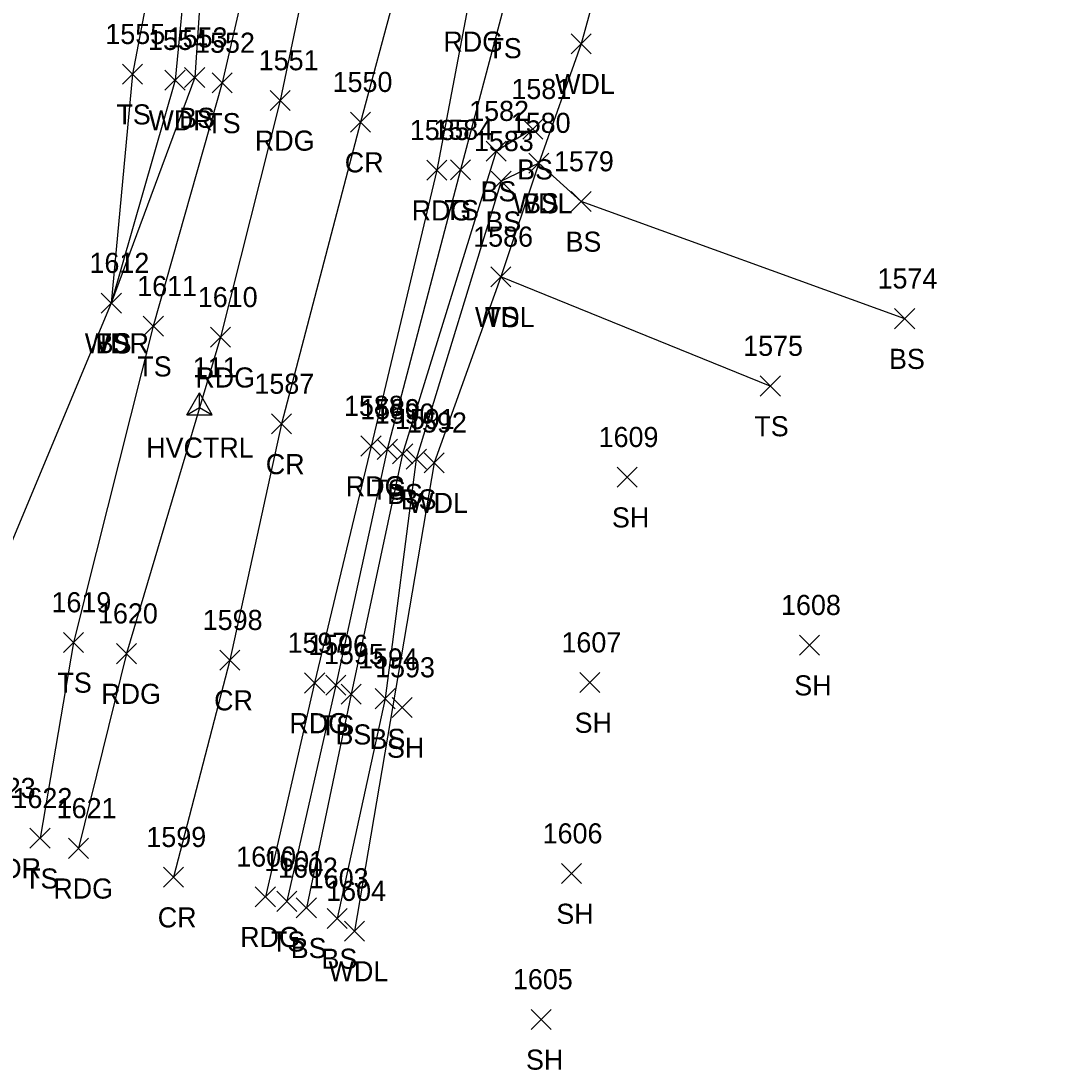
# Model space of a CAD drawing. Extents: x 1678553 to 1680768, y 787260 to 792325.
# Drawn here: x 1678621 to 1678723.5, y 787259.5 to 787363.9 of the extents above; entities that cross this region are included whole.
import ezdxf

# ---------------------------------------------------------------- set-up
doc = ezdxf.new("R2010")
doc.units = 0
for name, color, linetype in [('C_A', 7, 'Continuous'), ('C_I', 7, 'Continuous'), ('CPSM', 7, 'Continuous'), ('L_A', 7, 'Continuous'), ('L_I', 7, 'Continuous'), ('L_TIC', 7, 'Continuous'), ('LAWA', 7, 'Continuous'), ('LELB', 7, 'Continuous'), ('P_A', 7, 'Continuous'), ('P_I', 7, 'Continuous'), ('P_TIC', 7, 'Continuous'), ('PEU', 7, 'Continuous'), ('PRC', 7, 'Continuous')]:
    doc.layers.add(name, color=color, linetype=linetype)

msp = doc.modelspace()

# ---------------------------------------------------------------- linework, layer by layer
at = {"layer": 'CPSM'}
for p, q in [((1678637.53, 787324.73), (1678638.78, 787326.89)), ((1678640.03, 787324.73), (1678638.78, 787326.89)), ((1678638.78, 787325.45), (1678638.78, 787326.89)), ((1678637.53, 787324.73), (1678638.78, 787325.45)), ((1678637.53, 787324.73), (1678640.03, 787324.73)), ((1678638.78, 787325.45), (1678638.78, 787325.45)), ((1678638.78, 787325.45), (1678640.03, 787324.73))]:
    msp.add_line(p, q, dxfattribs=at)
at = {"layer": 'L_TIC'}
for points in [[(1678675.74, 787360.63), (1678677.74, 787362.63)], [(1678677.74, 787360.63), (1678675.74, 787362.63)], [(1678631.1, 787357.6), (1678633.1, 787359.6)], [(1678633.1, 787357.6), (1678631.1, 787359.6)], [(1678635.34, 787357.01), (1678637.34, 787359.01)], [(1678637.34, 787357.01), (1678635.34, 787359.01)], [(1678637.3, 787357.26), (1678639.3, 787359.26)], [(1678639.3, 787357.26), (1678637.3, 787359.26)], [(1678640.04, 787356.73), (1678642.04, 787358.73)], [(1678642.04, 787356.73), (1678640.04, 787358.73)], [(1678670.94, 787352.13), (1678672.94, 787354.13)], [(1678672.94, 787352.13), (1678670.94, 787354.13)], [(1678667.3, 787349.95), (1678669.3, 787351.95)], [(1678669.3, 787349.95), (1678667.3, 787351.95)], [(1678671.53, 787348.76), (1678673.53, 787350.76)], [(1678673.53, 787348.76), (1678671.53, 787350.76)], [(1678671.53, 787348.76), (1678673.53, 787350.76)], [(1678673.53, 787348.76), (1678671.53, 787350.76)], [(1678671.53, 787348.76), (1678673.53, 787350.76)], [(1678673.53, 787348.76), (1678671.53, 787350.76)], [(1678663.74, 787348.08), (1678665.74, 787350.08)], [(1678665.74, 787348.08), (1678663.74, 787350.08)], [(1678667.78, 787346.95), (1678669.78, 787348.95)], [(1678669.78, 787346.95), (1678667.78, 787348.95)], [(1678675.75, 787344.94), (1678677.75, 787346.94)], [(1678677.75, 787344.94), (1678675.75, 787346.94)], [(1678667.76, 787337.44), (1678669.76, 787339.44)], [(1678669.76, 787337.44), (1678667.76, 787339.44)], [(1678667.76, 787337.44), (1678669.76, 787339.44)], [(1678669.76, 787337.44), (1678667.76, 787339.44)], [(1678629, 787334.83), (1678631, 787336.83)], [(1678631, 787334.83), (1678629, 787336.83)], [(1678629, 787334.83), (1678631, 787336.83)], [(1678631, 787334.83), (1678629, 787336.83)], [(1678629, 787334.83), (1678631, 787336.83)], [(1678631, 787334.83), (1678629, 787336.83)], [(1678707.94, 787333.28), (1678709.94, 787335.28)], [(1678709.94, 787333.28), (1678707.94, 787335.28)], [(1678633.18, 787332.53), (1678635.18, 787334.53)], [(1678635.18, 787332.53), (1678633.18, 787334.53)], [(1678694.57, 787326.58), (1678696.57, 787328.58)], [(1678696.57, 787326.58), (1678694.57, 787328.58)], [(1678656.46, 787320.28), (1678658.46, 787322.28)], [(1678658.46, 787320.28), (1678656.46, 787322.28)], [(1678657.99, 787319.84), (1678659.99, 787321.84)], [(1678659.99, 787319.84), (1678657.99, 787321.84)], [(1678659.35, 787319.3), (1678661.35, 787321.3)], [(1678661.35, 787319.3), (1678659.35, 787321.3)], [(1678661.12, 787318.95), (1678663.12, 787320.95)], [(1678663.12, 787318.95), (1678661.12, 787320.95)], [(1678680.32, 787317.51), (1678682.32, 787319.51)], [(1678682.32, 787317.51), (1678680.32, 787319.51)], [(1678625.23, 787301.07), (1678627.23, 787303.07)], [(1678627.23, 787301.07), (1678625.23, 787303.07)], [(1678698.46, 787300.8), (1678700.46, 787302.8)], [(1678700.46, 787300.8), (1678698.46, 787302.8)], [(1678651.34, 787296.83), (1678653.34, 787298.83)], [(1678653.34, 787296.83), (1678651.34, 787298.83)], [(1678676.61, 787297.08), (1678678.61, 787299.08)], [(1678678.61, 787297.08), (1678676.61, 787299.08)], [(1678652.86, 787295.92), (1678654.86, 787297.92)], [(1678654.86, 787295.92), (1678652.86, 787297.92)], [(1678656.25, 787295.48), (1678658.25, 787297.48)], [(1678658.25, 787295.48), (1678656.25, 787297.48)], [(1678657.94, 787294.6), (1678659.94, 787296.6)], [(1678659.94, 787294.6), (1678657.94, 787296.6)], [(1678621.91, 787281.59), (1678623.91, 787283.59)], [(1678623.91, 787281.59), (1678621.91, 787283.59)], [(1678674.79, 787278.08), (1678676.79, 787280.08)], [(1678676.79, 787278.08), (1678674.79, 787280.08)], [(1678646.47, 787275.32), (1678648.47, 787277.32)], [(1678648.47, 787275.32), (1678646.47, 787277.32)], [(1678648.41, 787274.67), (1678650.41, 787276.67)], [(1678650.41, 787274.67), (1678648.41, 787276.67)], [(1678651.47, 787273.61), (1678653.47, 787275.61)], [(1678653.47, 787273.61), (1678651.47, 787275.61)], [(1678653.2, 787272.36), (1678655.2, 787274.36)], [(1678655.2, 787272.36), (1678653.2, 787274.36)], [(1678671.78, 787263.57), (1678673.78, 787265.57)], [(1678673.78, 787263.57), (1678671.78, 787265.57)]]:
    msp.add_lwpolyline(points, dxfattribs=at)
at = {"layer": 'LAWA'}
for points in [[(1678709.78, 787516.49), (1678712.28, 787497.22), (1678701.79, 787461.31), (1678703.15, 787457.42), (1678705.06, 787457.53), (1678706.33, 787458.18), (1678713.92, 787445.73), (1678717.92, 787439.61), (1678723.5, 787424.18), (1678713.91, 787402.7), (1678707.75, 787397.77), (1678697.86, 787399.45), (1678688.05, 787395.99), (1678683.78, 787387.21), (1678676.74, 787361.63), (1678672.53, 787349.76), (1678668.76, 787338.44), (1678662.12, 787319.95), (1678654.2, 787273.36)], [(1678664.87, 787478.76), (1678656.17, 787475.05), (1678649.55, 787452.64), (1678645.06, 787437.85), (1678645.53, 787417.53), (1678643.94, 787403.04), (1678640.14, 787385.56), (1678638.68, 787382.05), (1678636.34, 787358.01), (1678630, 787335.83), (1678617.26, 787305.35), (1678619.26, 787283.6)]]:
    msp.add_lwpolyline(points, dxfattribs=at)
at = {"layer": 'LELB'}
for points in [[(1678703.25, 787521.16), (1678708.08, 787504.89), (1678710.05, 787496.73), (1678699.74, 787468.92), (1678698.82, 787457.49), (1678706.75, 787433.93), (1678714.45, 787417.51), (1678705.65, 787404.22), (1678696.31, 787404.91), (1678687.53, 787400.61), (1678678.86, 787394.6), (1678669.01, 787365.19), (1678664.74, 787349.08), (1678657.46, 787321.28), (1678652.34, 787297.83), (1678647.47, 787276.32)], [(1678680.77, 787518.06), (1678676.3, 787498.71), (1678671.38, 787486.28), (1678667.84, 787478.11), (1678658.92, 787472.2), (1678652.16, 787452.17), (1678649.27, 787436.42), (1678649.32, 787416.12), (1678648.83, 787401.97), (1678646.78, 787382.69), (1678641.04, 787357.73), (1678634.18, 787333.53), (1678626.23, 787302.07), (1678622.91, 787282.59)], [(1678670.34, 787510.61), (1678668.53, 787502.63), (1678666.36, 787491.77), (1678660.38, 787481.94), (1678643.3, 787471.26), (1678637.93, 787460.78), (1678638.18, 787442.6), (1678641.03, 787418.21), (1678640, 787400.91), (1678637.64, 787392.16), (1678640.14, 787385.56), (1678638.3, 787358.26), (1678630, 787335.83)], [(1678606.34, 787416.23), (1678617.44, 787401.01), (1678626.85, 787385.47), (1678635.93, 787378.61), (1678632.1, 787358.6), (1678630, 787335.83)], [(1678671.94, 787353.13), (1678668.3, 787350.95), (1678658.99, 787320.84), (1678653.86, 787296.92), (1678649.41, 787275.67)], [(1678672.53, 787349.76), (1678668.78, 787347.95), (1678660.35, 787320.3), (1678657.25, 787296.48), (1678652.47, 787274.61)], [(1678708.94, 787334.28), (1678676.75, 787345.94), (1678672.53, 787349.76)], [(1678695.57, 787327.58), (1678668.76, 787338.44)]]:
    msp.add_lwpolyline(points, dxfattribs=at)
at = {"layer": 'P_TIC'}
for points in [[(1678645.8, 787354.99), (1678647.8, 787356.99)], [(1678647.8, 787354.99), (1678645.8, 787356.99)], [(1678653.8, 787352.83), (1678655.8, 787354.83)], [(1678655.8, 787352.83), (1678653.8, 787354.83)], [(1678661.4, 787348.05), (1678663.4, 787350.05)], [(1678663.4, 787348.05), (1678661.4, 787350.05)], [(1678639.87, 787331.43), (1678641.87, 787333.43)], [(1678641.87, 787331.43), (1678639.87, 787333.43)], [(1678645.93, 787322.81), (1678647.93, 787324.81)], [(1678647.93, 787322.81), (1678645.93, 787324.81)], [(1678654.84, 787320.61), (1678656.84, 787322.61)], [(1678656.84, 787320.61), (1678654.84, 787322.61)], [(1678630.51, 787299.96), (1678632.51, 787301.96)], [(1678632.51, 787299.96), (1678630.51, 787301.96)], [(1678640.79, 787299.31), (1678642.79, 787301.31)], [(1678642.79, 787299.31), (1678640.79, 787301.31)], [(1678649.23, 787297.04), (1678651.23, 787299.04)], [(1678651.23, 787297.04), (1678649.23, 787299.04)], [(1678625.74, 787280.59), (1678627.74, 787282.59)], [(1678627.74, 787280.59), (1678625.74, 787282.59)], [(1678635.19, 787277.72), (1678637.19, 787279.72)], [(1678637.19, 787277.72), (1678635.19, 787279.72)], [(1678644.33, 787275.77), (1678646.33, 787277.77)], [(1678646.33, 787275.77), (1678644.33, 787277.77)]]:
    msp.add_lwpolyline(points, dxfattribs=at)
at = {"layer": 'PEU'}
for points in [[(1678701.08, 787523.46), (1678691.86, 787521.67), (1678683.93, 787520.5), (1678679.42, 787498.09), (1678675.86, 787484.77), (1678672.35, 787466.03), (1678666.65, 787446.98), (1678662.98, 787430.65), (1678658.14, 787412.6), (1678657.12, 787400.24), (1678652, 787380.89), (1678646.8, 787355.99), (1678640.87, 787332.43), (1678631.51, 787300.96), (1678626.74, 787281.59)], [(1678701.08, 787523.46), (1678699.33, 787512.57), (1678697.82, 787495.04), (1678694.12, 787469.83), (1678689.97, 787450.94), (1678685.8, 787426.95), (1678675.55, 787395.19), (1678665.56, 787365.84), (1678662.4, 787349.05), (1678655.84, 787321.61), (1678650.23, 787298.04), (1678645.33, 787276.77)]]:
    msp.add_lwpolyline(points, dxfattribs=at)
at = {"layer": 'PRC'}
msp.add_lwpolyline([(1678691.86, 787521.67), (1678687.47, 787496.54), (1678683.41, 787472.73), (1678673.58, 787430.34), (1678667.07, 787403.39), (1678661.63, 787379.18), (1678654.8, 787353.83), (1678646.93, 787323.81), (1678641.79, 787300.31), (1678636.19, 787278.72)], dxfattribs=at)

# ---------------------------------------------------------------- texts
at = {"layer": 'C_A'}
msp.add_text('HVCTRL', height=2, dxfattribs=at).set_placement((1678633.47, 787320.45))
at = {"layer": 'C_I'}
msp.add_text('111', height=2, dxfattribs=at).set_placement((1678638.12, 787328.45))
at = {"layer": 'L_A'}
for s, p in [('TS', (1678667.42, 787360.19)), ('WDL', (1678674.16, 787356.63)), ('TS', (1678630.51, 787353.6)), ('WDR', (1678633.7, 787353.01)), ('BS', (1678636.74, 787353.26)), ('TS', (1678639.45, 787352.73)), ('BS', (1678670.38, 787348.13)), ('BS', (1678666.74, 787345.95)), ('WDL', (1678669.94, 787344.76)), ('BS', (1678670.97, 787344.76)), ('BS', (1678670.97, 787344.76)), ('TS', (1678663.15, 787344.08)), ('BS', (1678667.22, 787342.95)), ('BS', (1678675.19, 787340.94)), ('WDL', (1678666.18, 787333.44)), ('TS', (1678667.17, 787333.44)), ('WDR', (1678627.36, 787330.83)), ('TS', (1678628.41, 787330.83)), ('BS', (1678628.44, 787330.83)), ('BS', (1678707.38, 787329.28)), ('TS', (1678632.59, 787328.53)), ('TS', (1678693.98, 787322.58)), ('TS', (1678655.87, 787316.28)), ('BS', (1678657.43, 787315.84)), ('BS', (1678658.79, 787315.3)), ('WDL', (1678659.54, 787314.95)), ('SH', (1678679.81, 787313.51)), ('TS', (1678624.64, 787297.07)), ('SH', (1678697.95, 787296.8)), ('TS', (1678650.75, 787292.83)), ('SH', (1678676.1, 787293.08)), ('BS', (1678652.3, 787291.92)), ('BS', (1678655.69, 787291.48)), ('SH', (1678657.43, 787290.6)), ('WDR', (1678616.62, 787278.6)), ('TS', (1678621.32, 787277.59)), ('SH', (1678674.28, 787274.08)), ('TS', (1678645.88, 787271.32)), ('BS', (1678647.85, 787270.67)), ('BS', (1678650.91, 787269.61)), ('WDL', (1678651.62, 787268.36)), ('SH', (1678671.26, 787259.57))]:
    msp.add_text(s, height=2, dxfattribs=at).set_placement(p)
at = {"layer": 'L_I'}
for s, p in [('1555', (1678629.41, 787361.6)), ('1553', (1678635.61, 787361.26)), ('1554', (1678633.65, 787361.01)), ('1552', (1678638.34, 787360.73)), ('1581', (1678669.81, 787356.13)), ('1582', (1678665.61, 787353.95)), ('1580', (1678669.75, 787352.76)), ('1580', (1678669.75, 787352.76)), ('1580', (1678669.75, 787352.76)), ('1584', (1678662.04, 787352.08)), ('1583', (1678666.08, 787350.95)), ('1579', (1678674.05, 787348.94)), ('1586', (1678666.01, 787341.44)), ('1586', (1678666.01, 787341.44)), ('1612', (1678627.83, 787338.83)), ('1612', (1678627.83, 787338.83)), ('1612', (1678627.83, 787338.83)), ('1574', (1678706.24, 787337.28)), ('1611', (1678632.58, 787336.53)), ('1575', (1678692.87, 787330.58)), ('1589', (1678654.76, 787324.28)), ('1590', (1678656.21, 787323.84)), ('1591', (1678658.22, 787323.3)), ('1592', (1678659.43, 787322.95)), ('1609', (1678678.49, 787321.51)), ('1619', (1678624.05, 787305.07)), ('1608', (1678696.64, 787304.8)), ('1596', (1678649.59, 787300.83)), ('1607', (1678674.79, 787301.08)), ('1595', (1678651.16, 787299.92)), ('1594', (1678654.55, 787299.48)), ('1593', (1678656.25, 787298.6)), ('1623', (1678616.52, 787286.6)), ('1622', (1678620.17, 787285.59)), ('1606', (1678672.92, 787282.08)), ('1601', (1678645.21, 787279.32)), ('1602', (1678646.59, 787278.67)), ('1603', (1678649.65, 787277.61)), ('1604', (1678651.38, 787276.36)), ('1605', (1678669.96, 787267.57))]:
    msp.add_text(s, height=2, dxfattribs=at).set_placement(p)
at = {"layer": 'P_A'}
for s, p in [('RDG', (1678663.04, 787360.84)), ('RDG', (1678644.28, 787350.99)), ('CR', (1678653.23, 787348.83)), ('RDG', (1678659.89, 787344.05)), ('RDG', (1678638.36, 787327.43)), ('CR', (1678645.37, 787318.81)), ('RDG', (1678653.33, 787316.61)), ('RDG', (1678629, 787295.96)), ('CR', (1678640.23, 787295.31)), ('RDG', (1678647.72, 787293.04)), ('RDG', (1678624.23, 787276.59)), ('CR', (1678634.62, 787273.72)), ('RDG', (1678642.82, 787271.77))]:
    msp.add_text(s, height=2, dxfattribs=at).set_placement(p)
at = {"layer": 'P_I'}
for s, p in [('1551', (1678644.67, 787358.99)), ('1550', (1678652.02, 787356.83)), ('1585', (1678659.7, 787352.05)), ('1610', (1678638.61, 787335.43)), ('1587', (1678644.24, 787326.81)), ('1588', (1678653.15, 787324.61)), ('1620', (1678628.68, 787303.96)), ('1598', (1678639.1, 787303.31)), ('1597', (1678647.54, 787301.04)), ('1621', (1678624.57, 787284.59)), ('1599', (1678633.49, 787281.72)), ('1600', (1678642.43, 787279.77))]:
    msp.add_text(s, height=2, dxfattribs=at).set_placement(p)

doc.saveas('drawing.dxf')
